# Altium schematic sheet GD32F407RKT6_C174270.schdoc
size 127 x 101 mm
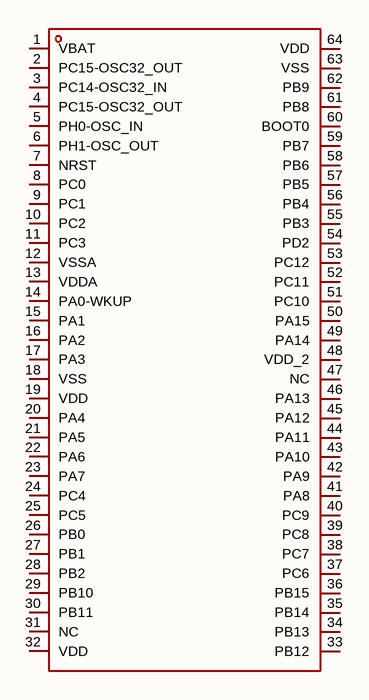
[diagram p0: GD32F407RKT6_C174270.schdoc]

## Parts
U?  gd32f407rkt6  [LQFP-64_L10.0-W10.0-P0.50-LS12.0-BL]  (value not drawn)

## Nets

Not connected (* = marked no-connect by the designer): U? 1(VBAT) 2(PC15-OSC32_OUT) 3(PC14-OSC32_IN) 4(PC15-OSC32_OUT) 5(PH0-OSC_IN) 6(PH1-OSC_OUT) 7(NRST) 8(PC0) 9(PC1) 10(PC2) 11(PC3) 12(VSSA) 13(VDDA) 14(PA0-WKUP) 15(PA1) 16(PA2) 17(PA3) 18(VSS) 19(VDD) 20(PA4) 21(PA5) 22(PA6) 23(PA7) 24(PC4) 25(PC5) 26(PB0) 27(PB1) 28(PB2) 29(PB10) 30(PB11) 31(NC) 32(VDD) 33(PB12) 34(PB13) 35(PB14) 36(PB15) 37(PC6) 38(PC7) 39(PC8) 40(PC9) 41(PA8) 42(PA9) 43(PA10) 44(PA11) 45(PA12) 46(PA13) 47(NC) 48(VDD_2) 49(PA14) 50(PA15) 51(PC10) 52(PC11) 53(PC12) 54(PD2) 55(PB3) 56(PB4) 57(PB5) 58(PB6) 59(PB7) 60(BOOT0) 61(PB8) 62(PB9) 63(VSS) 64(VDD)

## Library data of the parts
U? = gd32f407rkt6: Manufacturer: GigaDevice(兆易创新); Symbol: GD32F407RKT6_C174270; AddInBom: yes; ModelId: cd9de06618c44fcf82654c43a457f83c; ModelName: LQFP-64_L10.0-W10.0-H1.4-LS12.0-P0.50; ModelTransform: 472.441,472.441,0,0,0,0,0,0.465,0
